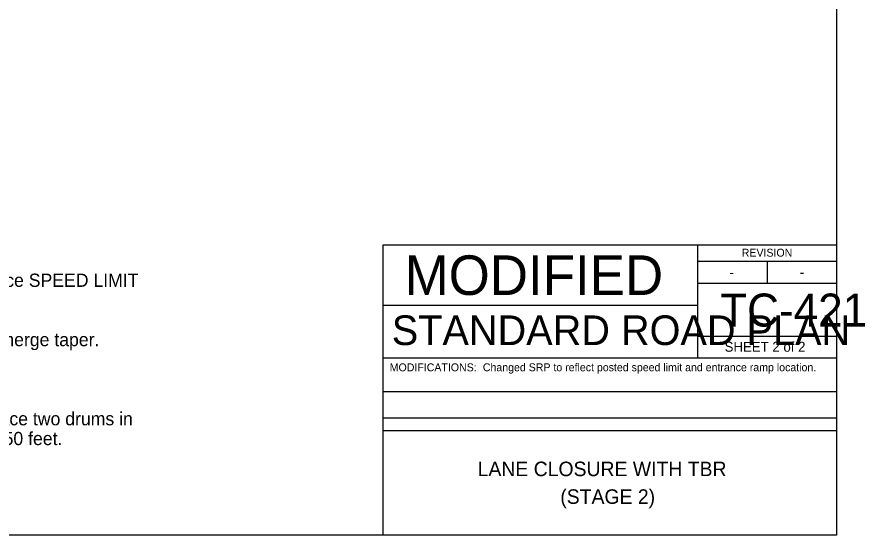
# Model space of a CAD drawing. Extents: x 10133 to 2270741, y 5363 to 1733450.
# Drawn here: x 30024 to 31311, y 7924 to 8710 of the extents above; entities that cross this region are included whole.
import ezdxf

# ---------------------------------------------------------------- set-up
doc = ezdxf.new("R2010")
doc.units = 0
for name, color, linetype in [('dsnStdDimension', 7, 'Continuous'), ('dsnStdLineWork', 7, 'Continuous'), ('dsnStdShading', 7, 'Continuous'), ('dsnStdTable', 7, 'Continuous'), ('SheetBorder', 7, 'Continuous')]:
    doc.layers.add(name, color=color, linetype=linetype)

msp = doc.modelspace()

# ---------------------------------------------------------------- linework, layer by layer
at = {"layer": 'dsnStdDimension'}
for p, q in [((31056.6, 8364), (31056.6, 8272.7)), ((31056.6, 8339.1), (31267.5, 8339.1)), ((31162.1, 8339.1), (31162.1, 8305.9)), ((31056.6, 8305.9), (31267.5, 8305.9)), ((30579.5, 8272.7), (31056.6, 8272.7)), ((31056.6, 8272.7), (31056.6, 8192.7)), ((31267.5, 8224.9), (31056.6, 8224.9)), ((30579.5, 8192.7), (31267.5, 8192.7)), ((30579.5, 8141.7), (31267.5, 8141.7)), ((30579.5, 8101.7), (31267.5, 8101.7)), ((30579.5, 8082.7), (31267.5, 8082.7))]:
    msp.add_line(p, q, dxfattribs=at)
msp.add_lwpolyline([(30579.5, 8364), (31267.5, 8364), (31267.5, 7924), (30579.5, 7924)], close=True, dxfattribs=at)
at = {"layer": 'dsnStdLineWork'}
msp.add_lwpolyline([(30579.5, 8364), (31267.5, 8364), (31267.5, 7924), (30579.5, 7924)], close=True, dxfattribs=at)
at = {"layer": 'SheetBorder'}
msp.add_lwpolyline([(28132.5, 9944), (31267.5, 9944), (31267.5, 7924), (28132.5, 7924)], close=True, dxfattribs=at)

# ---------------------------------------------------------------- texts
at = {"layer": 'dsnStdDimension'}
for s, height, p in [('REVISION', 12, (31123.6, 8346.2)), ('-', 15, (31105.1, 8314.7)), ('-', 15, (31211.6, 8315.1)), ('TC-421', 50, (31090.9, 8240.2)), ('STANDARD ROAD PLAN', 45.001, (30592.6, 8212.1)), ('SHEET 2 of 2', 15, (31097.6, 8202)), ('Changed SRP to reflect posted speed limit and entrance ramp location.', 12, (30730.8, 8172.4)), ('LANE CLOSURE WITH TBR', 22, (30722.9, 8013.3)), ('(STAGE 2)', 22, (30848.3, 7971.3))]:
    msp.add_text(s, height=height, dxfattribs=at).set_placement(p)
at = {"layer": 'dsnStdShading'}
msp.add_text('MODIFICATIONS:', height=12, dxfattribs=at).set_placement((30589.5, 8172.3))
at = {"layer": 'dsnStdTable'}
for s, p in [('Place SPEED LIMIT AHEAD sign and SPEED LIMIT 55 sign prior to the lane closure as shown. Place SPEED LIMIT', (28828.9, 8300.4)), ('For traffic control zones lasting more than 4 hours, place a Speed Feedback Sign at the end of the merge taper.', (28828.9, 8210.4)), ('For lanes closed to traffic, place two drums every 1000 feet. For full depth excavations in a closed lane, place two drums in ', (28748.9, 8090.4)), ('front of each location. Additional drums need not be placed for full depth excavations spaced closer than 150 feet.', (28748.9, 8060.4))]:
    msp.add_text(s, height=20, dxfattribs=at).set_placement(p)
at = {"layer": 'SheetBorder'}
msp.add_text('MODIFIED', height=60, dxfattribs=at).set_placement((30612.1, 8288.1))

doc.saveas('drawing.dxf')
